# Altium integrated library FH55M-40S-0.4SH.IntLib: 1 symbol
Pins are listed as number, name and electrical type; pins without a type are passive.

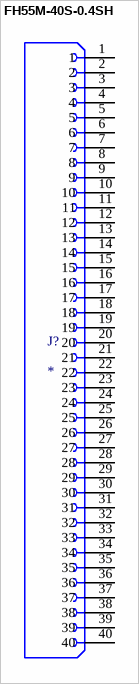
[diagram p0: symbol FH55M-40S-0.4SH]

## FH55M-40S-0.4SH
designator J?
MP: FH55M-40S-0.4SH
footprint HRS_FH55M-40S-0.4SH
pins: 1, 2, 3, 4, 5, 6, 7, 8, 9, 10, 11, 12, 13, 14, 15, 16, 17, 18, 19, 20, 21, 22, 23, 24, 25, 26, 27, 28, 29, 30, 31, 32, 33, 34, 35, 36, 37, 38, 39, 40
